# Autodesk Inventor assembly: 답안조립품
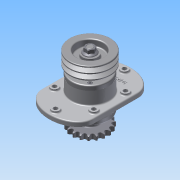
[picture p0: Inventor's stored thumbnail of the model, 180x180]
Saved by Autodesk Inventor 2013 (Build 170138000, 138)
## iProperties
Created: 2015-02
Part Number: 답안조립품
Document SubType Name: Assembly
Designer: Administrator
Author: Administrator
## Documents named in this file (12)
- C:\Documents and Settings\Administrator\바탕 화면\450208V1012\답안조립품.iam
- C:\Documents and Settings\Administrator\바탕 화면\450208V1012\1-본체.ipt
- C:\Documents and Settings\Administrator\바탕 화면\450208V1012\6-베어링 6206.ipt
- C:\Documents and Settings\Administrator\바탕 화면\450208V1012\3-축.ipt
- C:\Documents and Settings\Administrator\바탕 화면\450208V1012\7-부시.ipt
- C:\Documents and Settings\Administrator\바탕 화면\450208V1012\2-커버.ipt
- C:\Documents and Settings\Administrator\바탕 화면\450208V1012\8-오일실 30x42.ipt
- C:\Documents and Settings\Administrator\바탕 화면\450208V1012\11-키 6x6.ipt
- C:\Documents and Settings\Administrator\바탕 화면\450208V1012\9-M16-너트.ipt
- C:\Documents and Settings\Administrator\바탕 화면\450208V1012\4-V벨트풀리.ipt
- C:\Documents and Settings\Administrator\바탕 화면\450208V1012\5-체인 스프로킷.ipt
- C:\Documents and Settings\Administrator\바탕 화면\450208V1012\10-M6.ipt
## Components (23 placed, 11 different names)
1. 1-본체:1
2. 6-베어링 6206:1
3. 3-축:1 — 각도:1, 각도:2, 각도:4, 각도:6
4. 7-부시:1
5. 6-베어링 6206:2
6. 2-커버:1
7. 2-커버:2
8. 8-8-오일실 30x42:1
9. 8-8-오일실 30x42:2
10. 11-키 6x6:1 — 각도:1, 각도:5
11. 11-키 6x6:2 — 각도:2, 각도:3
12. 9-M16 너트:1 — 각도:4
13. 4-V벨트풀리:1 — 각도:3
14. 5-체인 스프로킷:1 — 각도:5
15. 9-M16 너트:2 — 각도:6
16. 10-M6:2
17. 10-M6:3
18. 10-M6:4
19. 10-M6:5
20. 10-M6:1
21. 10-M6:6
22. 10-M6:7
23. 10-M6:8
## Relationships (6: Angle 6)
- 각도:1 [Angle]: 3-축:1 ↔ 11-키 6x6:1
- 각도:2 [Angle]: 3-축:1 ↔ 11-키 6x6:2
- 각도:3 [Angle]: 11-키 6x6:2 ↔ 4-V벨트풀리:1
- 각도:4 [Angle]: 3-축:1 ↔ 9-M16 너트:1
- 각도:5 [Angle]: 11-키 6x6:1 ↔ 5-체인 스프로킷:1
- 각도:6 [Angle]: 3-축:1 ↔ 9-M16 너트:2
